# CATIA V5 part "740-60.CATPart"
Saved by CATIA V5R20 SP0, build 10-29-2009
Part number: 740-60
Bounding box of the stored display mesh (mm): x -47.4 to 47.4, y -44.5 to 47.4, z -60 to 20
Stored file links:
  C:\Users\Utente\Desktop\IO LAVORO\3D X SITO CF\X SITO\740\740-60.CATPart
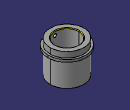
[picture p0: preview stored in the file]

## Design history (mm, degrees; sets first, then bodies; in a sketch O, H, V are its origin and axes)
Set1
  DatumSurface1 to DatumSurface35 "740-60"
Body1 (main body)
